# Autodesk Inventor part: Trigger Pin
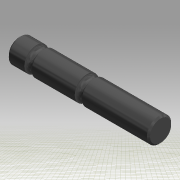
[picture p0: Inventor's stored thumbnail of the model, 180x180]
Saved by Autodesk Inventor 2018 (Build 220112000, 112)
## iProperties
Part Number: Trigger Pin
Material: SolidWorks Materials|AISI 316 Annealed Stainless Steel Bar (SS)
Document SubType Name: Modeling
Designer: johne
Density: 8 g/cm^3
Appearance: Default
Author: johne
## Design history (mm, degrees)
feature "Body1"
body "Solid1"
